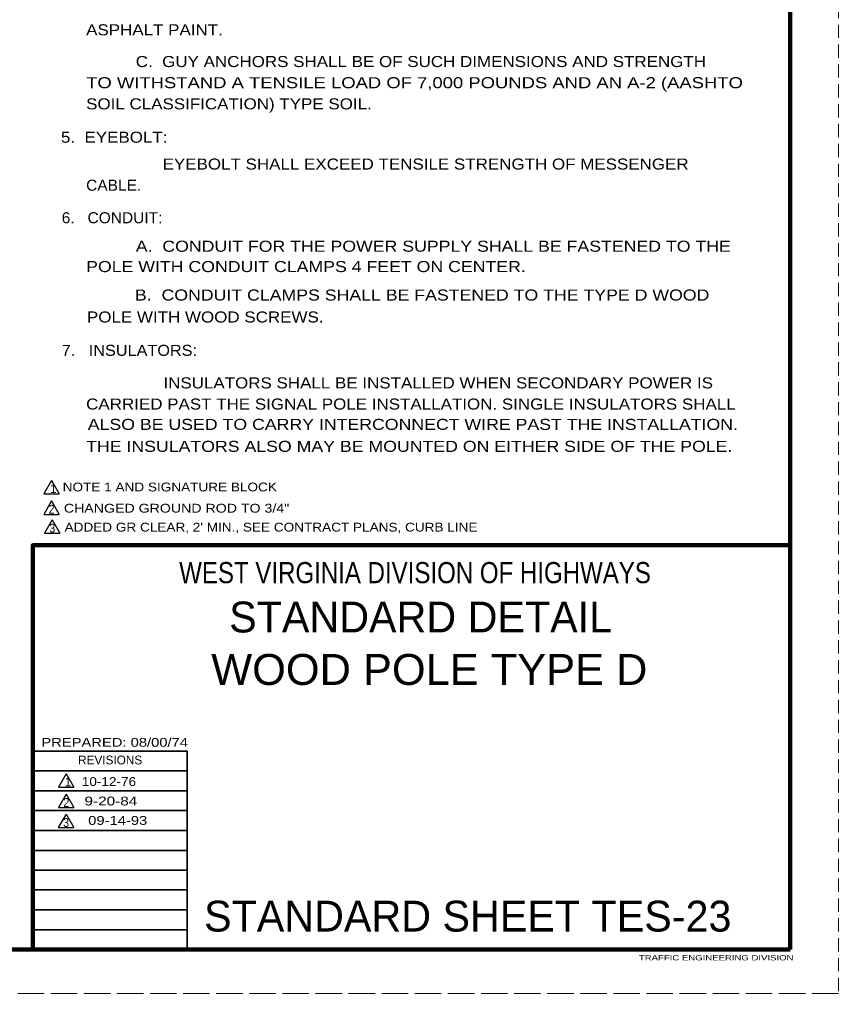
# Model space of a CAD drawing. Extents: x 12366 to 13046, y 9129 to 9570.
# Drawn here: x 12860.4 to 13046, y 9129.5 to 9350.2 of the extents above; entities that cross this region are included whole.
import ezdxf
from ezdxf.enums import TextEntityAlignment as Align

# ---------------------------------------------------------------- set-up
doc = ezdxf.new("R2010")
doc.units = 0
doc.linetypes.add('LONG_DASHED', pattern=[7.5, 6, -1.5])
doc.linetypes.add('MEDIUM_DASHED', pattern=[4.5, 3, -1.5])
doc.layers.add('1', color=7, linetype='Continuous', lineweight=53)
doc.layers.add('61', color=7, linetype='Continuous', lineweight=35)

msp = doc.modelspace()

# ---------------------------------------------------------------- linework, layer by layer
at = {"layer": '1', "linetype": 'MEDIUM_DASHED', "lineweight": 13}
msp.add_line((13046.012, 9569.533), (13045.992, 9129.513), dxfattribs=at)
at = {"layer": '1', "lineweight": 25}
for p, q in [((12867.648, 9245.719), (12865.898, 9242.688)), ((12867.648, 9245.719), (12869.398, 9242.688)), ((12865.898, 9242.688), (12869.398, 9242.688)), ((12867.648, 9241.109), (12865.898, 9238.078)), ((12867.648, 9241.109), (12869.398, 9238.078)), ((12865.898, 9238.078), (12869.398, 9238.078)), ((12867.813, 9236.826), (12866.063, 9233.795)), ((12867.813, 9236.826), (12869.563, 9233.795)), ((12866.063, 9233.795), (12869.563, 9233.795)), ((12871.001, 9179.275), (12869.251, 9176.244)), ((12871.001, 9179.275), (12872.751, 9176.244)), ((12869.251, 9176.244), (12872.751, 9176.244)), ((12871.001, 9174.665), (12869.251, 9171.634)), ((12871.001, 9174.665), (12872.751, 9171.634)), ((12869.251, 9171.634), (12872.751, 9171.634)), ((12870.942, 9170.111), (12869.192, 9167.08)), ((12870.942, 9170.111), (12872.692, 9167.08)), ((12869.192, 9167.08), (12872.692, 9167.08))]:
    msp.add_line(p, q, dxfattribs=at)
at = {"layer": '1', "lineweight": 35}
for p, q in [((12898.392, 9179.933), (12863.412, 9179.933)), ((12898.392, 9175.433), (12863.412, 9175.433)), ((12898.392, 9170.933), (12863.412, 9170.933)), ((12898.392, 9166.413), (12863.412, 9166.413)), ((12898.392, 9161.933), (12863.412, 9161.933)), ((12898.392, 9157.453), (12863.412, 9157.453)), ((12898.392, 9152.953), (12863.412, 9152.953)), ((12898.392, 9148.453), (12863.412, 9148.453)), ((12898.392, 9143.933), (12863.412, 9143.933))]:
    msp.add_line(p, q, dxfattribs=at)
at = {"layer": '1', "lineweight": 158}
msp.add_lwpolyline([(12863.392, 9139.493), (12863.392, 9231.073), (13035.052, 9231.073)], dxfattribs=at)
at = {"layer": '1', "lineweight": 35}
msp.add_lwpolyline([(12898.392, 9139.453), (12898.392, 9184.413), (12863.412, 9184.413)], dxfattribs=at)
at = {"layer": '61', "lineweight": 158}
for p, q in [((13035.032, 9559.533), (13035.052, 9139.493)), ((13035.052, 9139.493), (12395.992, 9139.513))]:
    msp.add_line(p, q, dxfattribs=at)
at = {"layer": '61', "linetype": 'LONG_DASHED', "lineweight": 13}
msp.add_line((13045.992, 9129.513), (12365.932, 9129.493), dxfattribs=at)

# ---------------------------------------------------------------- texts
at = {"layer": '1'}
for s, height, width, p in [('ASPHALT PAINT.', 2.5, 1.15, (12875.505, 9346.627)), ('C.  GUY ANCHORS SHALL BE OF SUCH DIMENSIONS AND STRENGTH', 2.5, 1.15, (12886.751, 9339.437)), ('TO WITHSTAND A TENSILE LOAD OF 7,000 POUNDS AND AN A-2 (AASHTO', 2.5, 1.25, (12875.505, 9334.643)), ('SOIL CLASSIFICATION) TYPE SOIL.', 2.5, 1.15, (12875.505, 9329.85)), ('5.  EYEBOLT:', 2.5, 1.15, (12869.79, 9322.291)), ('EYEBOLT SHALL EXCEED TENSILE STRENGTH OF MESSENGER ', 2.5, 1.15, (12892.835, 9316.208)), ('CABLE.', 2.5, 1.05, (12875.505, 9311.414)), ('6.   CONDUIT:', 2.5, 1.05, (12869.974, 9304.04)), ('A.  CONDUIT FOR THE POWER SUPPLY SHALL BE FASTENED TO THE', 2.5, 1.2, (12886.751, 9297.587)), ('POLE WITH CONDUIT CLAMPS 4 FEET ON CENTER.', 2.5, 1.2, (12875.505, 9292.978)), ('B.  CONDUIT CLAMPS SHALL BE FASTENED TO THE TYPE D WOOD', 2.5, 1.2, (12886.567, 9286.526)), ('POLE WITH WOOD SCREWS.', 2.5, 1.15, (12875.69, 9281.548)), ('7.   INSULATORS:', 2.5, 1.1, (12869.975, 9273.989)), ('INSULATORS SHALL BE INSTALLED WHEN SECONDARY POWER IS', 2.5, 1.15, (12893.019, 9266.615)), ('CARRIED PAST THE SIGNAL POLE INSTALLATION. SINGLE INSULATORS SHALL', 2.5, 1.15, (12875.505, 9261.822)), ('ALSO BE USED TO CARRY INTERCONNECT WIRE PAST THE INSTALLATION.', 2.5, 1.2, (12875.874, 9257.213)), ('THE INSULATORS ALSO MAY BE MOUNTED ON EITHER SIDE OF THE POLE.', 2.5, 1.2, (12875.505, 9252.235)), ('2', 2, 0.9, (12866.992, 9238.23)), ('CHANGED GROUND ROD TO 3/4"', 2, 1.2, (12870.462, 9238.461)), ('3', 2, 0.9, (12867.157, 9233.947)), ("ADDED GR CLEAR, 2' MIN., SEE CONTRACT PLANS, CURB LINE", 2, 1.15, (12870.626, 9234.178)), ('PREPARED: 08/00/74', 1.998, 1.25, (12865.352, 9185.413)), ('10-12-76', 2, 1.15, (12874.516, 9176.526)), ('9-20-84', 2, 1.3, (12875.117, 9172.117)), ('3', 2, 0.9, (12870.286, 9167.231)), ('TRAFFIC ENGINEERING DIVISION', 1.2, 1.35, (13000.772, 9136.993))]:
    msp.add_text(s, height=height, dxfattribs=dict(at, width=width)).set_placement(p)
for s, height, p in [('1', 2, (12867.305, 9242.889)), ('REVISIONS', 1.998, (12873.672, 9181.413)), ('1', 2, (12870.658, 9176.477)), ('STANDARD SHEET TES-23', 6.993, (12902.232, 9143.533))]:
    msp.add_text(s, height=height, dxfattribs=at).set_placement(p)
for s, height, width, p in [('NOTE 1 AND SIGNATURE BLOCK', 2, 1.15, (12894.462, 9243.271)), ('WEST VIRGINIA DIVISION OF HIGHWAYS', 4.795, 0.85, (12950.04, 9222.473)), ('WOOD POLE TYPE D', 7, 1.05, (12953.269, 9199.424)), ('2', 2, 0.9, (12871.009, 9171.79)), ('09-14-93', 2, 1.25, (12882.666, 9167.718))]:
    msp.add_text(s, height=height, dxfattribs=dict(at, width=width)).set_placement(p, align=Align.CENTER)
msp.add_text('STANDARD DETAIL', height=6.993, dxfattribs=at).set_placement((12951.309, 9211.313), align=Align.CENTER)

doc.saveas('drawing.dxf')
